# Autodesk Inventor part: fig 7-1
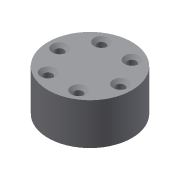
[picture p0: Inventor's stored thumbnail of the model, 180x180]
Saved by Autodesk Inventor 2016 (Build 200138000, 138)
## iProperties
Created: 2004-05
Part Number: fig 7-1
Document SubType Name: Modeling
Designer: CADCIM Technologies
Manufacturer: Standard
Standards Organization: Custom
Density: 1 g/cm^3
Material: Generic
Appearance: Default
Author: CADCIM Technologies
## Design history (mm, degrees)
sketch "Sketch1"
  geometry: C1 r 17.175 at (0, 0)
  constraints: 1 centre point
extrude "Extrusion1" new body sketch "Sketch1" distance "d0" = 17; taper "d1" = 0 deg
sketch "Sketch2"
  geometry: 1 further point
hole "Hole1" sketch "Sketch2" at (12.571, -0.074) diameter "d2" = 3.5; stored, may be unused: countersink angle "d6" = 90 deg, drill point angle "d8" = 118 deg; dims "d3" = 6, "d4" = 6, "d5" = 2, "d7" = 8
pattern_circular "Circular Pattern1" dims angle "d11" = 360 deg
body "Solid1"
